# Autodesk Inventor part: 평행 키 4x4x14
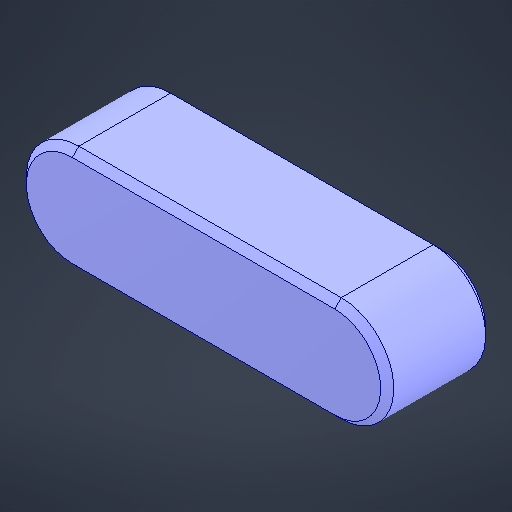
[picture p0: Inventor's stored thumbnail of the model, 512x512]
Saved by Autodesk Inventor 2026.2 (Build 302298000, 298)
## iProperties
Created: 2026-06
Part Number: 평행 키 4x4x14
Material: 강철, 연강
Description: 키 및 해당 키홈
Document SubType Name: Modeling
Designer: sec7
Density: 7.85 g/cm^3
Appearance: 기본값
Author: jhkim
Sending System: Autodesk Inventor 2027
Preprocessor: ST-DEVELOPER v20.1
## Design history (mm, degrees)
feature "Solid1"
node "솔리드1"
